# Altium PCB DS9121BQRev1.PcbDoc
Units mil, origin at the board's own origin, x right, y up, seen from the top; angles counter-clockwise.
Board outline 2000 x 2000 mil, 2 copper layers (Top Layer, Bottom Layer); 26 components, 14 nets, 76 pads, 11 vias.
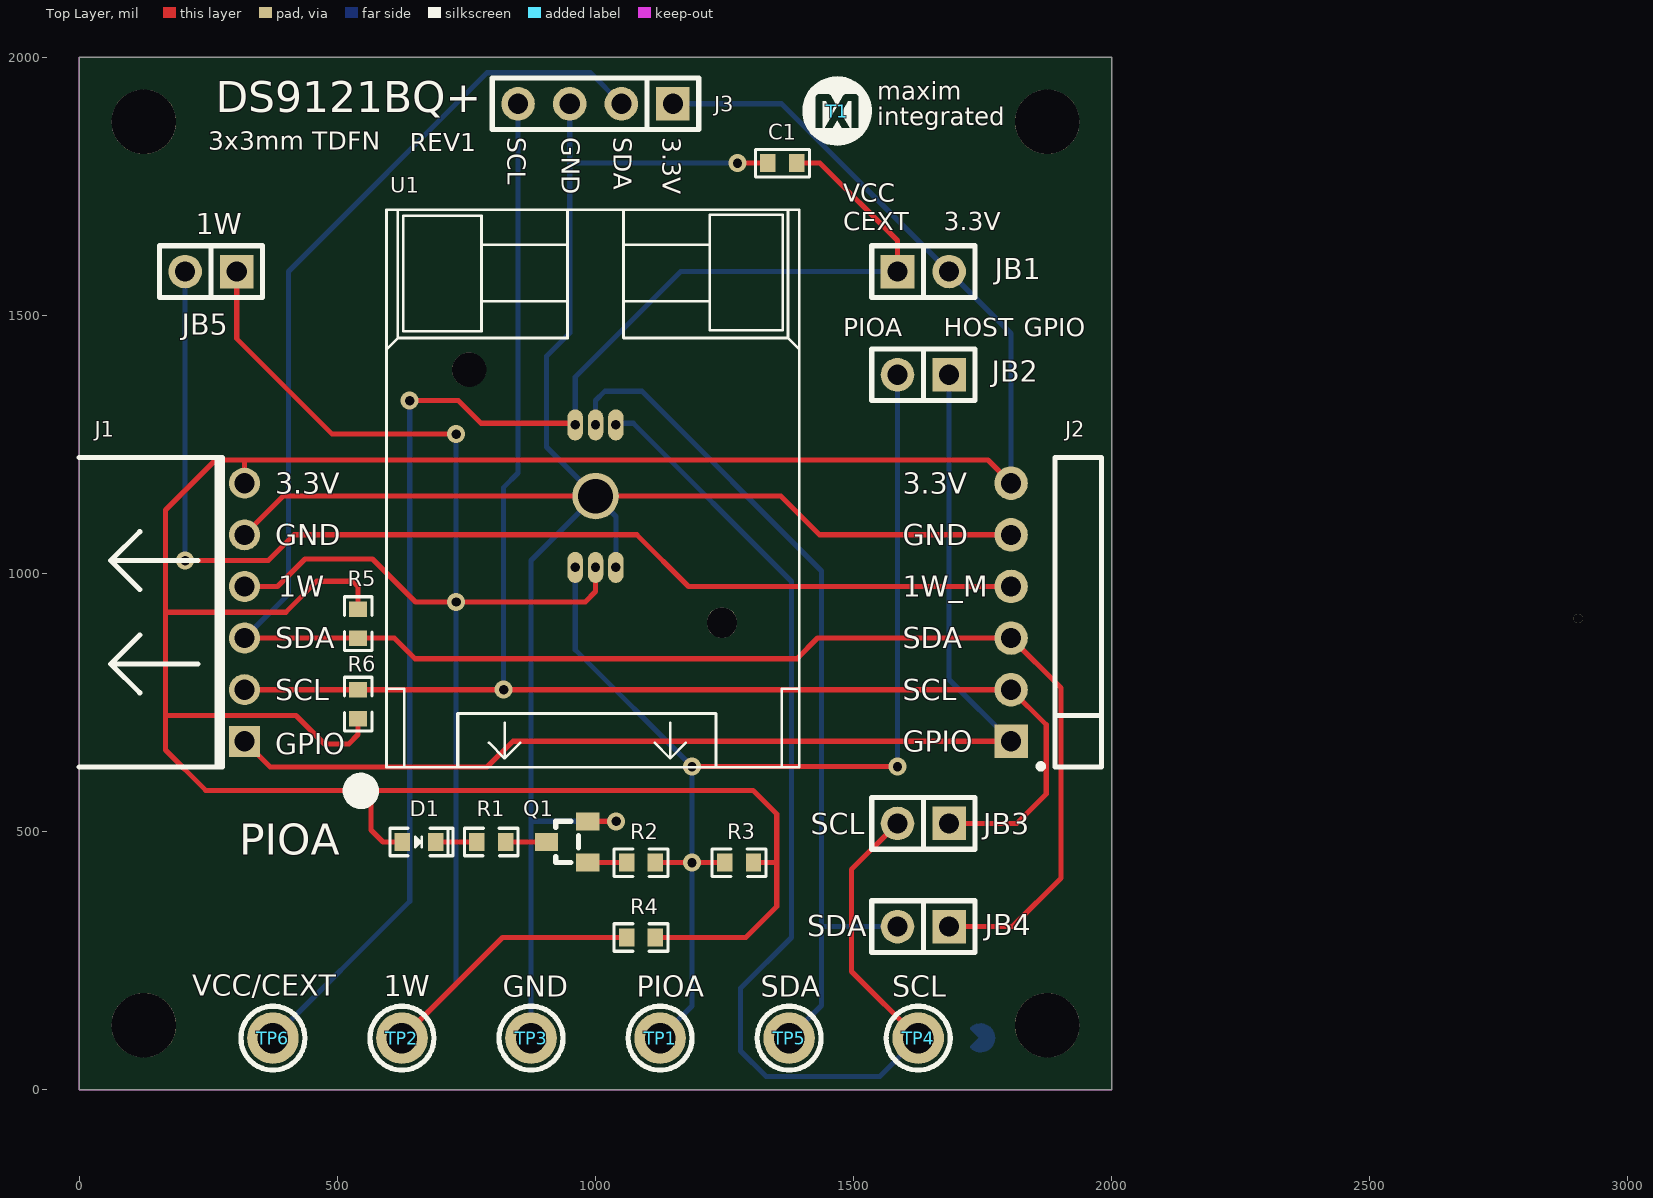
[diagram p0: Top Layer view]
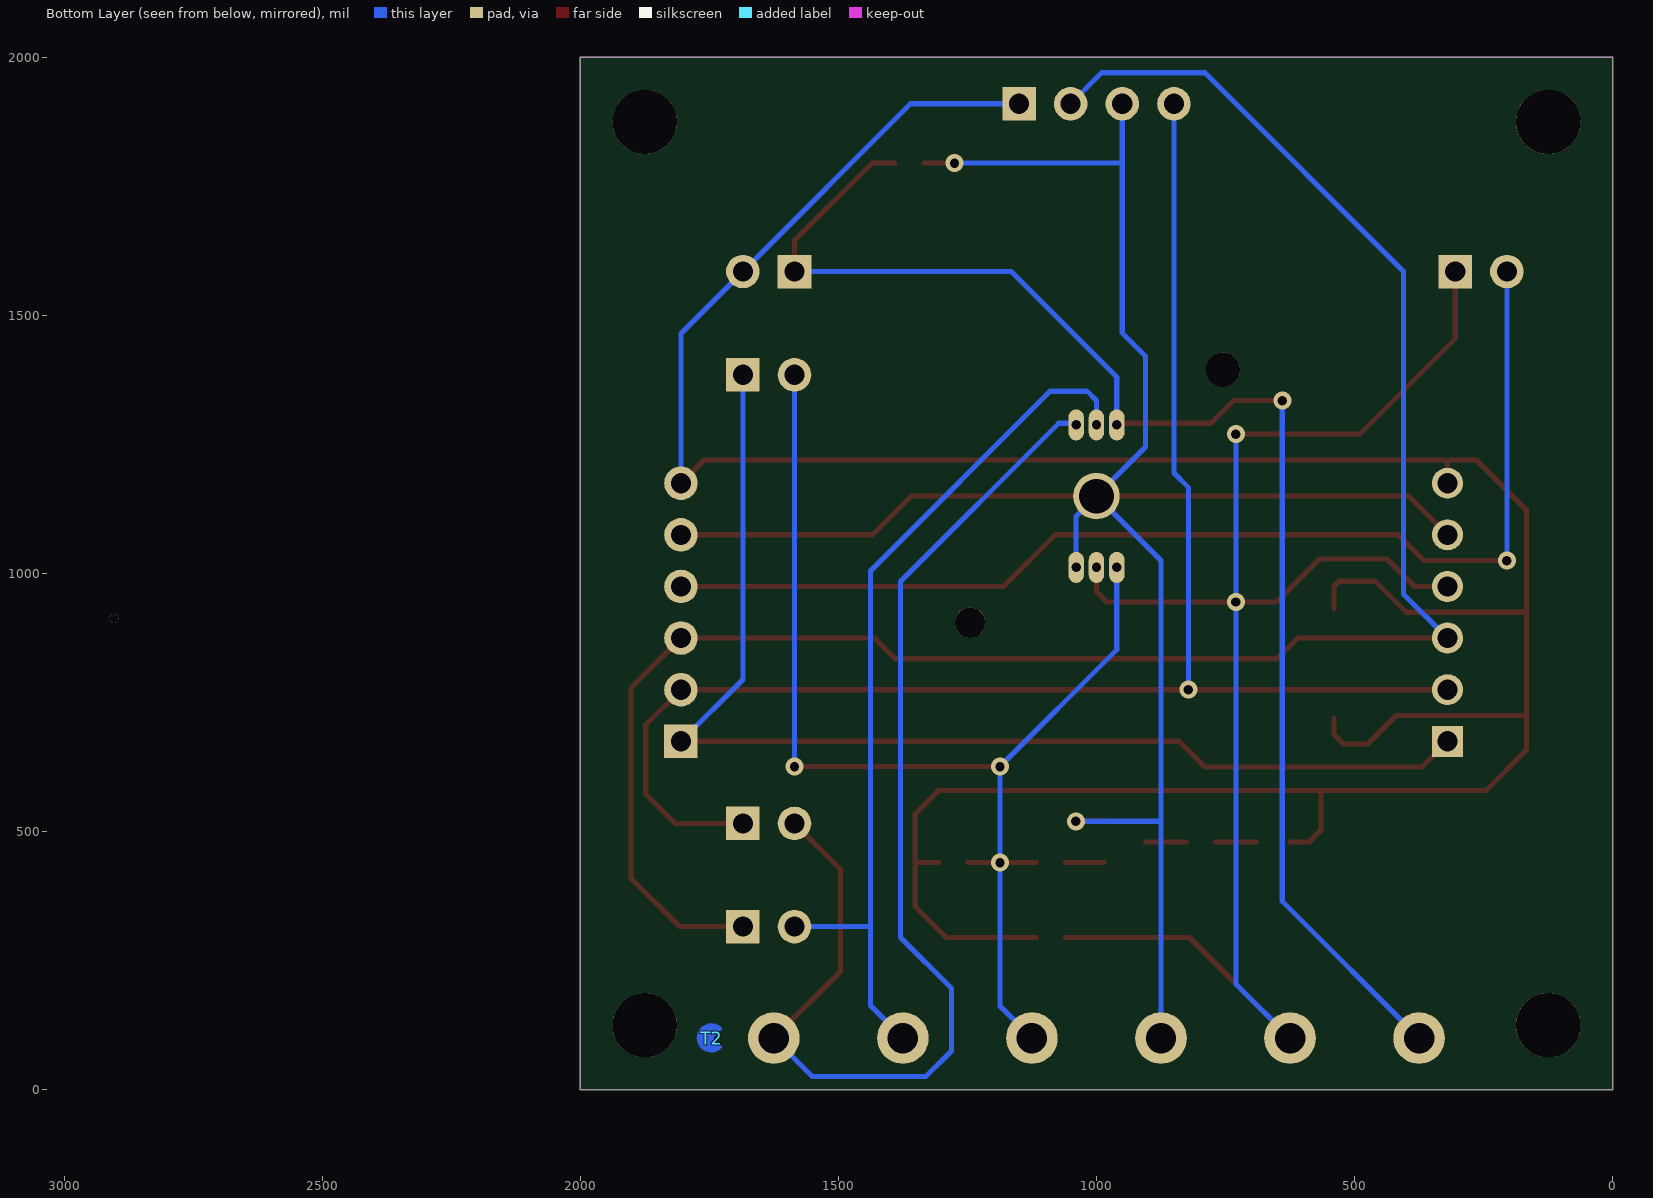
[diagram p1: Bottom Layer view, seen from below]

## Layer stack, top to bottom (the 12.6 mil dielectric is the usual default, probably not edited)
Top Layer: signal copper 1.4
Dielectric: dielectric 12.6, FR-4, Dk 4.8
Bottom Layer: signal copper 1.4

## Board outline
0,0 0,2000 2000,2000 2000,0

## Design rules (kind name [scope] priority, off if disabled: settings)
Clearance [All] p1: gap=9
ComponentClearance [All] p1: gap=2 collisioncheckmode=3 verticalgap=10 showdistances=FALSE
HoleSize [All] p1: absolutevalues=TRUE maxlimit=1000 minlimit=1 maxpercent=80.000 minpercent=20.000
MinimumSolderMaskSliver [All] p1: minsoldermaskwidth=0
PolygonConnect [All] p1: connectstyle=Relief reliefconductorwidth=10 reliefentries=4 polygonreliefangle="90 Angle"
RoomDefinition DS9121BQRev1 [InComponentClass('DS9121BQRev1')] p1: confinementstyle=ConfineIn formatcopy=TRUE lockcomponents=FALSE outline -143,-60 2040,-60 2040,2039 -143,2039
RoutingVias [All] p1: holewidth=13 width=35 viastyle="Through Hole" minholewidth=13 minwidth=35 maxholewidth=28 maxwidth=50
SilkToSilkClearance [All] p1: silktosilkclearance=0
SilkscreenOverComponentPads [All] p1: minsilkscreentomaskgap=5
SolderMaskExpansion [All] p1: expansion=4
Width [All] p1: maxlimit=1111 minlimit=1 preferedwidth=25
23 further rules are at their usual default settings.

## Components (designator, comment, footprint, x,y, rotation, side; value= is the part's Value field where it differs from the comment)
C1 "470nF" CAP0603-3D 1390,1795 r180 top
D1 "GREEN LED" 0603LED-3DGREEN 690,480 r180 top
J1 "PMOD Input" SIP6-SOCKET2-LA-3D 320,675 r90 top
J2 "PMOD Output" SIP6-HEADER-RA-LH-3D 1805,675 r90 top
J3 "I2C PORT (DNP)" SIP4 1150,1910 r180 top
JB1 "JUMPBLOCK 1" SIP2-3D 1585,1585 r0 top
JB2 "JUMPBLOCK 1" SIP2-3D 1685,1385 r180 top
JB3 "JUMPBLOCK 1" SIP2-3D 1685,516 r180 top
JB4 "JUMPBLOCK 1" SIP2-3D 1685,316 r180 top
JB5 "JUMPBLOCK 1" SIP2SHUNT-3D 305,1585 r180 top
Q1 "BSS138LT1G" 16001-3D 985,440 r90 top
R1 "10K" 0603-3D 770,480 r0 top
R2 "3.3k" 0603-3D 1060,440 r0 top
R3 "10k" 0603-3D 1250,440 r0 top
R4 "DNP" 0603 1060,295 r0 top
R5 "DNP" 0603 540,875 r90 top
R6 "DNP" 0603 540,775 r270 top
T1 "PAC" LOGOMAXNEWSMALL 1468,1896 r0 top
T2 "PAC" PAC 1745,100 r180 bottom
TP1 "TP" TP-3D 1125,100 r180 top
TP2 "TP" TP-3D 625,100 r180 top
TP3 "TP" TP-3D 875,100 r180 top
TP4 "TP" TP-3D 1625,100 r180 top
TP5 "TP" TP-3D 1375,100 r180 top
TP6 "TP" TP-3D 375,100 r180 top
U1 "DS28E50" "TDFN6 3X2mm .95p BURN" 1000,1150 r90 top locked

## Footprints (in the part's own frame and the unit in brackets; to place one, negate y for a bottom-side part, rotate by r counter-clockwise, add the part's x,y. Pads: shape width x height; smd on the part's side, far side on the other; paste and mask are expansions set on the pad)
0603 [mil]
  rect 30x35 smd: 1(0,0) 2(56,0)
  silkscreen extent -24,-27 80,27
0603-3D [mil]
  rect 30x35 smd: 1(0,0) 2(56,0)
  silkscreen extent -24,-27 80,27, body extent -3,-17 59,17, height 18
0603LED-3DGREEN [mil]
  rect 30x35 smd: 1(0,0) 2(64,0)
  silkscreen extent -34,-27 88,27, body extent 0,-16 64,15, height 24
16001-3D [mil]
  rect 35x45 smd: 1(0,0) 2(80,0) 3(40,80)
  silkscreen extent 0,18 80,62, body extent -19,-21 99,97, height 51
CAP0603-3D [mil]
  rect 30x35 smd: 1(0,0) 2(56,0)
  silkscreen extent -24,-27 80,27, body extent -3,-16 59,16, height 31
LOGOMAXNEWSMALL [mil]
  silkscreen extent -67,-67 67,67
PAC [mil]
  Top Layer region: 0,1.49 0,0 17.57,-17.57 17.57,-17.86 14.76,-20.67 9.84,-23.62 3.94,-25.59 0.46,-26.06 -3.04,-26.2 -7,-25.65 -10.83,-24.61 -13.46,-23.32 -15.75,-21.65 -17.37,-20.24 -19.67,-18.17 -21.65,-15.75 -23.48,-13.48 -24.92,-10.75 -26.1,-7.85 -26.57,-4.92 -26.91,-0.28 -26.83,3.93 -26.37,6.84 -25.59,9.84 -23.62,13.78 -19.68,18.7 -14.76,22.64 -10.83,24.61 -5.82,26.22 0.98,26.57 5.91,25.59 11.47,23.71 17.32,18.81
  Top Layer lines w5: 0,0 17.57,-17.57 cw(c-1,0.49) 17.32,18.81 0,1.49
SIP2-3D [mil]
  rect 65x65 hole 39: 1(0,0)
  round 65 hole 39: 2(100,0)
  silkscreen extent -50,-50 150,50, body extent -46,-49 154,49, height 244
SIP2SHUNT-3D [mil]
  rect 65x65 hole 39: 1(0,0)
  round 65 hole 39: 2(100,0)
  silkscreen extent -50,-50 150,50, body extent -46,-49 154,49, height 583
SIP4 [mil]
  rect 65x65 hole 39: 1(0,0)
  round 65 hole 39: 2(100,0) 3(200,0) 4(300,0)
  silkscreen extent -50,-50 350,50
SIP6-HEADER-RA-LH-3D [mil]
  rect 65x65 hole 39: 1(0,0)
  round 65 hole 39: 2(100,0) 3(200,0) 4(300,0) 5(400,0) 6(500,0)
  silkscreen extent -54,-175 550,-52, body extent -50,-195 550,13, height 140
SIP6-SOCKET2-LA-3D [mil]
  rect 60x60 hole 39: 1(0,0)
  round 60 hole 39: 2(100,0) 3(200,0) 4(300,0) 5(400,0) 6(500,0)
  silkscreen extent -50,43 550,320, body extent -51,-13 550,398, height 100
"TDFN6 3X2mm .95p BURN" [mil]
  oval 60x30 hole 18: 1(-138,39.37) 2(-138,0) 3(-138,-39.37) 4(138,-39.37) 5(138,0) 6(138,39.37)
  round 90 hole 67: EP(0,0)
  round 0 hole 59 unplated: HOLE(-245,-245)
  round 0 hole 67 unplated: HOLE(245,245)
  silkscreen extent -525,-395 555,405
TP-3D [mil]
  round 100 hole 59: 1(0,0)
  silkscreen extent -62,-62 62,62, body extent -63,-63 62,62, height 220

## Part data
C1: library part CAP
D1: library part LED, "LED INGAN GREEN CLEAR 0603 SMD"
J1: library part CON6, "CONN RCPT .100\" 6POS R/A SGL SN"
J2: library part CON6, "CONN HEADER FEMALE 6POS .1\" GOLD"
J3: library part CON4, "4 Pin 100mil Female Connector"
Q1: library part "NCHAN FET", "MOSFET N-CH 50V 200MA SOT-23"
R1: library part RESISTOR, "RES SMD 1K OHM 1% 1/10W 0603"
R2: library part RESISTOR, "RES 3.3K OHM 1/10W 1% 0603 SMD"
R3 R4 R5 R6: library part RESISTOR, "RES SMD 10K OHM 1% 1/10W 0603"
TP1 TP2 TP3 TP4 TP5 TP6: "Test Point"

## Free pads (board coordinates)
  round 0 hole 125 unplated: NPTH(125,125) NPTH(125,1875) NPTH(1875,125) NPTH(1875,1875)
  round 125 all layers, no hole: ""(125,125) ""(125,1875) ""(1875,125) ""(1875,1875)
  round 66 all layers, no hole: ""(755,1395)
  round 59 all layers, no hole: ""(1245,905)
  round 0 hole 125 unplated mask+1.18: ""(2907.87,-38.9)
  round 0 hole 67 mask+1.18: ""(2907.87,119.1)
  round 0 hole 67 unplated mask+1.18: ""(2907.87,277.1)
  round 0 hole 59 unplated mask+1.18: ""(2907.87,435.1)
  round 0 hole 59 mask+1.18: ""(2907.87,593.1)
  round 0 hole 39 mask+1.18: ""(2907.87,751.1)

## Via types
v1: diameter 35, hole 18, Top Layer to Bottom Layer, tented both sides, 6 vias
v2: diameter 35, hole 18, Top Layer to Bottom Layer, 4 vias
v3: diameter 18, hole 18, Top Layer to Bottom Layer, tented both sides, 1 vias

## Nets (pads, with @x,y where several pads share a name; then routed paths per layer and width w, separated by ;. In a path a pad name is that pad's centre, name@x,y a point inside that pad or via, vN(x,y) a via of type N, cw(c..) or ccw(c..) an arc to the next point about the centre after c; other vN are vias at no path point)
1W_M: J2.4 JB5.2 | length 2222.1
  Top Layer w10: v2(205,1025) 366,1025 416,1075 1080,1075 1180,975 J2.4
  Bottom Layer w10: v2(205,1025) JB5.2
3.3V: D1.2 J1.6 J2.6 J3.1 JB1.2 R3.2 R4.2 R5.2 R6.2 | length 6083.1
  Top Layer w10: J1.6 320,1220 ; R6.2 540,688 522,670 475,670 420,725 167,725 ; R5.2 540,975 530,985 460,985 400,925 167,925 ; D1.2 588,480 565,503 565,580 ; R4.2 1291,295 1351,355 1351,440 ; R3.2 1351,440 ; J2.6 1760,1220 320,1220 ; 167,725 167,925 ; 167,725 167,658 245,580 565,580 ; 167,925 167,1123 264,1220 320,1220 ; 565,580 1305,580 1351,534 1351,440
  Bottom Layer w10: J3.1 1360,1910 JB1.2 1805,1465 J2.6
GND: C1.2 J1.5 J2.5 J3.3 Q1.2 TP3.1 U1.3 U1.EP | length 4228.2
  Top Layer w10: J1.5 395,1150 U1.EP 1358.75,1150 1433.75,1075 J2.5 ; Q1.2 v1(1040,520) ; v1(1275,1795) C1.2
  Bottom Layer w10: TP3.1 875,520 ; J3.3 950,1795 ; U1.3@1039.37,1009 U1.3 1039.37,1110.63 U1.EP ; v1(1040,520) 875,520 ; v1(1275,1795) 950,1795 ; 875,520 875,1025 U1.EP ; 950,1795 950,1466 905,1421 905,1245 U1.EP
GPIO: J1.1 J2.1 JB2.1 | length 2286.1
  Top Layer w10: J1.1 370,625 790,625 840,675 J2.1
  Bottom Layer w10: JB2.1 1685,795 J2.1
IO_1W: J1.4 JB5.1 R4.1 TP2.1 U1.2 | length 3149.5
  Top Layer w10: JB5.1 305,1455 490,1270 v1(730,1270) ; J1.4 384,975 437,1028 568,1028 651,945 v1(730,945) 980,945 1000,965 U1.2@1000,1009 ; TP2.1 820,295 R4.1
  Bottom Layer w10: TP2.1 730,205 v1(730,945) v1(730,1270)
NetD1_1: D1.1 R1.1 | length 80
  Top Layer w10: D1.1 R1.1
NetQ1_1: Q1.1 R2.1 | length 75
  Top Layer w10: Q1.1 R2.1
NetQ1_3: Q1.3 R1.2 | length 79
  Top Layer w10: R1.2 Q1.3
PIOA: JB2.2 R2.2 R3.1 TP1.1 U1.1 | length 2319.4
  Top Layer w10: R2.2 R3.1 ; v2(1187,626) v2(1585,626)
  Bottom Layer w10: U1.1@960.63,1009 960.63,852.37 v2(1187,626) v2(1187,440) 1187,162 TP1.1 ; v2(1585,626) JB2.2
SCL: J1.2 J2.2 J3.4 JB3.1 R6.1 | length 3073.4
  Top Layer w10: J1.2 R6.1 v1(822,775) J2.2 1873,707 1873,573 1816,516 JB3.1
  Bottom Layer w10: v1(822,775) 822,1167 850,1195 J3.4
SCL/TCK: JB3.2 TP4.1 U1.4 | length 2318.6
  Top Layer w10: JB3.2 1496,427 1496,229 TP4.1
  Bottom Layer w10: U1.4@1039.37,1291 1073,1291 1379.5,984.5 1379.5,295 1281,196.5 1281,75 1330,26 1551,26 TP4.1
SDA: J1.3 J2.3 J3.2 JB4.1 R5.1 | length 3853.8
  Top Layer w10: J1.3 610,875 650,835 1390,835 1430,875 J2.3 1902,778 1902,410 1808,316 JB4.1
  Bottom Layer w10: J1.3 405,960 405,1585 790,1970 990,1970 J3.2
SDA/TDO: JB4.2 TP5.1 U1.5 | length 1711.7
  Bottom Layer w10: U1.5@1000,1291 1000,1335 1018,1353 1090,1353 1438,1005 1438,316 ; TP5.1 1438,163 1438,316 ; JB4.2 1438,316
VCC/CEXT: C1.1 JB1.1 TP6.1 U1.6 | length 2799.4
  Top Layer w10: v1(640,1335) 734,1335 778,1291 U1.6@960.63,1291 ; C1.1 1435,1795 1585,1645 JB1.1
  Bottom Layer w10: TP6.1 640,365 v1(640,1335) ; U1.6@960.63,1291 960.63,1380.63 1165,1585 JB1.1
pads on no net: U1.HOLE
copper on no net:
  other v3: 2903.87,913.1

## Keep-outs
Keep-Out Layer:
  the board outline again, w1

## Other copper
Top Layer:
  text "TOP METAL" at 300,-640 h70
Bottom Layer:
  text "Bottom Metal" at 300,-840 h70
  text "Bottom Metal" at 2760,-840 h70

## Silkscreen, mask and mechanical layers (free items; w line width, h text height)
Top Overlay:
  circle w35: c545.37,579 r17.63
  text "DS9121BQ+" at 264,1894 h60
  text "SCL" at 830,1845 h35 r270
  text "GND" at 935,1845 h35 r270
  text "SDA" at 1035,1845 h35 r270
  text "3.3V" at 1130,1845 h35 r270
  text "3x3mm TDFN" at 250,1821 h35
  text "REV1" at 640.5,1818.35 h35
  text "VCC" at 1480,1720 h35
  text "CEXT" at 1480,1665 h35
  text "3.3V" at 1675,1665 h35
  text "1W" at 226,1657 h40
  text "PIOA" at 1480,1460 h35
  text "HOST" at 1675,1460 h35
  text "GPIO" at 1830,1460 h35
  text "3.3V" at 380,1155 h40
  text "3.3V" at 1595,1155 h40
  text "GND" at 380,1055 h40
  text "GND" at 1595,1055 h40
  text "1W" at 385,955 h40
  text "1W_M" at 1595,955 h40
  text "SDA" at 380,855 h40
  text "SDA" at 1595,855 h40
  text "SCL" at 380,755 h40
  text "SCL" at 1595,755 h40
  text "GPIO" at 1595,655 h40
  text "GPIO" at 380,650 h40
  text "SCL" at 1417,495 h40
  text "PIOA" at 310,455 h60
  text "SDA" at 1410,297 h40
  text "VCC/CEXT" at 219,182 h40
  text "1W" at 590,181 h40
  text "GND" at 820,180 h40
  text "PIOA" at 1080,180 h40
  text "SDA" at 1320,180 h40
  text "SCL" at 1575,180 h40
  text "Top Silk Screen" at 300,-400 h70
Bottom Overlay:
  text "Bottom Silk Screen" at 300,-1080 h70
  text "Bottom Silk Screen" at 2760,-1080 h70
Top Solder:
  text "Top Solder Mask" at 300,-520 h70
Bottom Solder:
  text "Bottom Solder Mask" at 300,-960 h70
  text "Bottom Solder Mask" at 2760,-960 h70
Mechanical 1:
  lines w1: 1000,1910 1000,2000
Mechanical 11:
  lines w6: 512.4,849.92 512.4,954.08 565.6,954.08 565.6,849.92 512.4,849.92 ; 514.4,693.92 514.4,798.08 567.6,798.08 567.6,693.92 514.4,693.92 ; 792.92,1866 792.92,1957.6 1193,1957.6 1193,1866 792.92,1866 ; 1034.92,268.4 1139.08,268.4 1139.08,321.6 1034.92,321.6 1034.92,268.4
  text "TOP ASSEMBLY" at -93,2179 h200
  text "DNP" at 916,1884 h60
  text "DNP" at 554,859 h30 r90
  text "DNP" at 556,703 h30 r90
  text "DNP" at 1044,280 h30
Mechanical 31:
  drawing of 160 lines, arcs and shapes, not listed
  text "Notes:" at 3969.87,1956.1 h50
  text "DS9121BQ+" at 2623.7,1918.6 h50
  text "Part Number: 89-9121B+Q00" at 2450.87,1815.1 h50
  text "1." at 3969.87,1806.1 h50
  text "N/A" at 4116.87,1806.1 h50
  text "Property of" at 2689.87,1710.1 h50
  text "Rev" at 3615.87,1675.1 h50
  text "2." at 3969.87,1606.1 h50
  text "Material: RoHS Compliant FR-408 or similar laminate material" at 4119.87,1606.1 h50
  text "maxim" at 2866.46,1565.67 h120
  text "1" at 3667.87,1518.1 h50
  text "3." at 3969.87,1506.1 h50
  text "Board Dimensions: (2000 x 2000 mils)" at 4119.87,1506.1 h50
  text "integrated" at 2866.46,1467.67 h120
  text "TM" at 3345.87,1459.1 h30
  text "4." at 3969.87,1406.1 h50
  text "Board Thickness: 62 mils +/- 10%" at 4119.87,1406.1 h50
  text "5." at 3969.87,1306.1 h50
  text "Layers: 2 (Top, Bottom)" at 4119.87,1306.1 h50
  text "Drill and Mechanical Layer" at 2452.87,1305.1 h50
  text "Date:FEB 28 2018" at 2362.87,1209.1 h50
  text "Units in mils" at 3197.87,1207.1 h50
  text "6." at 3969.87,1206.1 h50
  text "Minimum Trace/Spacing: 10mil / 7mil" at 4119.87,1206.1 h50
  text "7." at 3969.87,1106.1 h50
  text "Copper Thickness: 1oz on all layers" at 4119.87,1106.1 h50
  text "SIZE" at 2393.87,1011.1 h50
  text "QTY" at 2660.87,1011.1 h50
  text "SYM" at 2838.87,1011.1 h50
  text "PLATED" at 3033.87,1011.1 h50
  text "TOLERANCE" at 3358.87,1011.1 h50
  text "8." at 3969.87,1006.1 h50
  text "Surface mount pads:19   Through Hole Pads:39  Nonplated through holes:6" at 4119.87,1006.1 h50
  text "9." at 3969.87,906.1 h50
  text "Soldermask: GREEN" at 4119.87,906.1 h50
  text "16" at 2685,885 h50
  text "18" at 2437.87,882.1 h50
  text "YES" at 3096.87,882.1 h50
  text "+/- 0.003" at 3361.87,881.1 h50
  text "10." at 3969.87,806.1 h50
  text "Legend: White. top side only" at 4119.87,806.1 h50
  text "YES" at 3101,726 h50
  text "26" at 2685,725 h50
  text "39" at 2437.87,724.1 h50
  text "+/- 0.003" at 3361.87,723.1 h50
  text "11." at 3969.87,706.1 h50
  text "Plating: Must be Lead free and RoHS Compliant" at 4119.87,706.1 h50
  text "12." at 3969.87,606.1 h50
  text "Finish: Most Economical Lead free and RoHS compliant process" at 4119.87,606.1 h50
  text "YES" at 3101,568 h50
  text "59" at 2437.87,566.1 h50
  text "6" at 2710,565 h50
  text "+/- 0.003" at 3361.87,565.1 h50
  text "13." at 3969.87,506.1 h50
  text "Vendor Logo & date code: Allowed on bottom side only" at 4119.87,506.1 h50
  text "NO" at 3101,410 h50
  text "59" at 2437.87,408.1 h50
  text "+/- 0.003" at 3361.87,407.1 h50
  text "14." at 3969.87,406.1 h50
  text "Through holes: quantity 55, Slot holes 0, minimum size 18 mil" at 4119.87,406.1 h50
  text "1" at 2715,405 h50
  text "15." at 3969.87,306.1 h50
  text "Tolerances:" at 4119.87,306.1 h50
  text "1" at 2715,255 h50
  text "NO" at 3101,252 h50
  text "67" at 2437.87,250.1 h50
  text "+/- 0.003" at 3361.87,249.1 h50
  text "Plated-through holes" at 4019.87,206.1 h50
  text "+/- 3 mil" at 5419.87,206.1 h50
  text "Pattern to pattern" at 4019.87,106.1 h50
  text "+/- 6 mil" at 5419.87,106.1 h50
  text "1" at 2715,97 h50
  text "YES" at 3101,94 h50
  text "67" at 2437.87,92.1 h50
  text "+/- 0.003" at 3361.87,91.1 h50
  text "Legend to legend" at 4019.87,6.1 h50
  text "no preference" at 5419.87,6.1 h50
  text "4" at 2715,-61 h50
  text "NO" at 3101,-64 h50
  text "125" at 2437.87,-65.9 h50
  text "+/- 0.003" at 3361.87,-66.9 h50
  text "Soldermask to pattern" at 4019.87,-93.9 h50
  text "+/- 6 mil" at 5419.87,-93.9 h50
  text "16." at 3969.87,-193.9 h50
  text "Electrical testing needed:" at 4119.87,-193.9 h50
  text "YES" at 5419.87,-193.9 h50
  text "62mil PCB" at 2160,-620 h70

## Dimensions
2000,2000 to 2000,0 on Mechanical 16
0,2000 to 2000,2000 on Mechanical 16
